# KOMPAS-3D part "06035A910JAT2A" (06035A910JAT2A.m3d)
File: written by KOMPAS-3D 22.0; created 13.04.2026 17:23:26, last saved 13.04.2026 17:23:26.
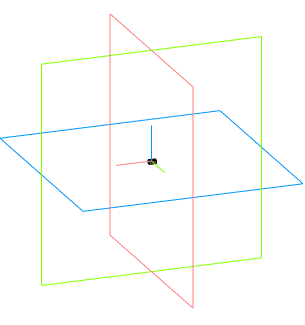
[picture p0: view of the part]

Document properties: Автор: Andrey; Полное имя файла: C:\Users\User1\Documents\06035A910JAT2A.m3d

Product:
- Part/product: 06035A910JAT2A

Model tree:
1. Операция без истории:1
2. Операция без истории:2
3. Операция без истории:3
